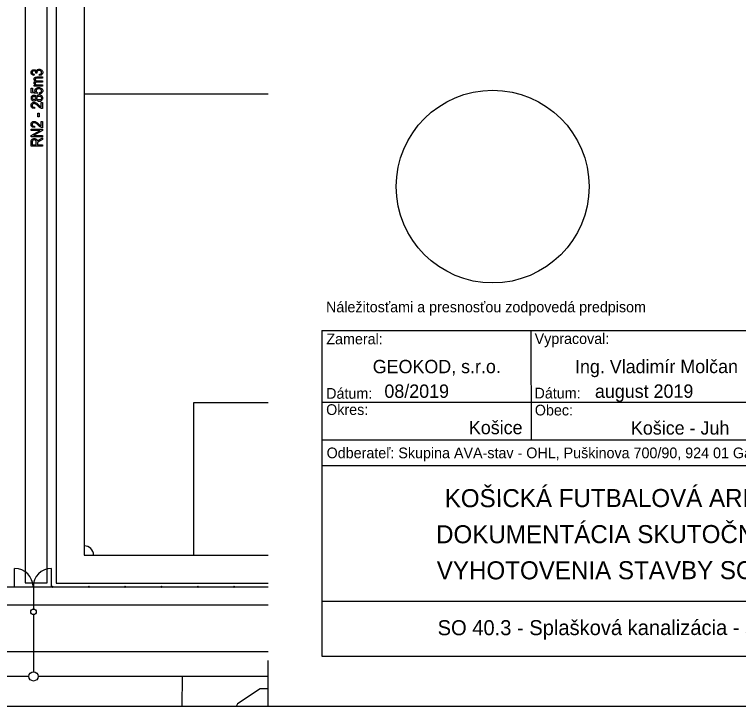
# Model space of a CAD drawing. Extents: x -264125 to -263915, y -1242307 to -1242159.
# Drawn here: x -264047.1 to -263968.6, y -1242307.4 to -1242232.4 of the extents above; entities that cross this region are included whole.
import ezdxf

# ---------------------------------------------------------------- set-up
doc = ezdxf.new("R2010")
doc.units = 0
for name, color, linetype in [('KFA_JESTV_IS_DSP', 7, 'Continuous'), ('KFA_SITUACIA_DSP', 7, 'Continuous'), ('RAM_NA_TLAC_A3_1-500', 7, 'Continuous'), ('ROZPISKA', 7, 'Continuous')]:
    doc.layers.add(name, color=color, linetype=linetype)

msp = doc.modelspace()

# ---------------------------------------------------------------- linework, layer by layer
at = {"layer": 'KFA_JESTV_IS_DSP'}
for p, q in [((-264020.458, -1242305.503), (-264022.907, -1242307.109)), ((-264019.579, -1242305.481), (-264020.458, -1242305.503)), ((-264022.907, -1242307.109), (-264023.062, -1242307.413))]:
    msp.add_line(p, q, dxfattribs=at)
at = {"layer": 'KFA_SITUACIA_DSP'}
for p, q in [((-264042.568, -1242187.932), (-264042.568, -1242294.032)), ((-264039.518, -1242190.982), (-264039.518, -1242290.982)), ((-264045.927, -1242194.982), (-264045.927, -1242293.982)), ((-264043.527, -1242293.982), (-264043.527, -1242194.982)), ((-264019.579, -1242240.982), (-264039.518, -1242240.982)), ((-264019.579, -1242274.482), (-264027.678, -1242274.482)), ((-264027.678, -1242274.482), (-264027.678, -1242290.982)), ((-264039.518, -1242290.982), (-264019.579, -1242290.982)), ((-264047.068, -1242294.432), (-264047.068, -1242292.432)), ((-264043.068, -1242294.432), (-264043.068, -1242292.432)), ((-264045.927, -1242293.982), (-264043.527, -1242293.982)), ((-264045.017, -1242293.982), (-264045.027, -1242296.847)), ((-264042.568, -1242294.032), (-264019.579, -1242294.032)), ((-264118.068, -1242294.432), (-264045.118, -1242294.432)), ((-264045.568, -1242294.432), (-264044.568, -1242294.432)), ((-264045.118, -1242294.432), (-264019.579, -1242294.432)), ((-264042.908, -1242294.432), (-264043.028, -1242294.432)), ((-264042.968, -1242294.492), (-264042.968, -1242294.372)), ((-264038.969, -1242294.432), (-264039.089, -1242294.432)), ((-264039.029, -1242294.492), (-264039.029, -1242294.372)), ((-264035.03, -1242294.432), (-264035.15, -1242294.432)), ((-264035.09, -1242294.492), (-264035.09, -1242294.372)), ((-264031.091, -1242294.432), (-264031.211, -1242294.432)), ((-264031.151, -1242294.492), (-264031.151, -1242294.372)), ((-264027.152, -1242294.432), (-264027.272, -1242294.432)), ((-264027.212, -1242294.492), (-264027.212, -1242294.372)), ((-264023.213, -1242294.432), (-264023.333, -1242294.432)), ((-264023.273, -1242294.492), (-264023.273, -1242294.372)), ((-264019.579, -1242296.432), (-264120.018, -1242296.432)), ((-264045.027, -1242297.447), (-264045.027, -1242303.647)), ((-264019.579, -1242301.482), (-264112.961, -1242301.482)), ((-264045.527, -1242304.147), (-264094.527, -1242304.147)), ((-264019.579, -1242304.147), (-264044.527, -1242304.147)), ((-264028.893, -1242307.413), (-264028.89, -1242304.147))]:
    msp.add_line(p, q, dxfattribs=at)
for points in [[(-264044.946, -1242238.832), (-264044.973, -1242238.957)], [(-264044.634, -1242238.721), (-264044.769, -1242238.707), (-264044.767, -1242238.687)], [(-264044.663, -1242239.118), (-264044.042, -1242239.118), (-264044.042, -1242239.244), (-264044.613, -1242239.244)], [(-264044.373, -1242238.97), (-264044.393, -1242238.844)], [(-264044.042, -1242240.126), (-264044.947, -1242240.126), (-264044.947, -1242240.013), (-264044.821, -1242240.013)], [(-264044.568, -1242239.559), (-264044.042, -1242239.559), (-264044.042, -1242239.685), (-264044.631, -1242239.685)], [(-264044.512, -1242240), (-264044.042, -1242240), (-264044.042, -1242240.126)], [(-264044.615, -1242240.818), (-264044.633, -1242240.937), (-264045.276, -1242240.837), (-264045.276, -1242240.328), (-264045.129, -1242240.328), (-264045.129, -1242240.738), (-264044.793, -1242240.792)], [(-264044.369, -1242240.959), (-264044.383, -1242240.827)], [(-264044.919, -1242242.413), (-264044.935, -1242242.542)], [(-264044.19, -1242241.888), (-264044.042, -1242241.888), (-264044.042, -1242242.566)], [(-264044.19, -1242242.391), (-264044.19, -1242241.888)], [(-264044.418, -1242243.439), (-264044.572, -1242243.439), (-264044.572, -1242243.053), (-264044.418, -1242243.053), (-264044.418, -1242243.439)], [(-264044.19, -1242243.959), (-264044.042, -1242243.959), (-264044.042, -1242244.637)], [(-264044.19, -1242244.462), (-264044.19, -1242243.959)], [(-264044.042, -1242245.607), (-264045.292, -1242245.607), (-264045.292, -1242245.468), (-264044.311, -1242244.929), (-264045.292, -1242244.929), (-264045.292, -1242244.8), (-264044.042, -1242244.8), (-264044.042, -1242244.938), (-264045.022, -1242245.476), (-264044.042, -1242245.476), (-264044.042, -1242245.607)], [(-264044.919, -1242244.483), (-264044.935, -1242244.612)], [(-264044.042, -1242246.637), (-264045.292, -1242246.637), (-264045.292, -1242246.182)], [(-264045.154, -1242246.177), (-264045.154, -1242246.501), (-264044.74, -1242246.501)], [(-264044.74, -1242246.501), (-264044.74, -1242246.209)], [(-264044.597, -1242246.345), (-264044.597, -1242246.501), (-264044.042, -1242246.501), (-264044.042, -1242246.637)], [(-264044.382, -1242245.912), (-264044.042, -1242245.733), (-264044.042, -1242245.904), (-264044.302, -1242246.04)]]:
    msp.add_lwpolyline(points, dxfattribs=at)
for centre, radius in [((-264042.968, -1242294.432), 0.06), ((-264039.029, -1242294.432), 0.06), ((-264035.09, -1242294.432), 0.06), ((-264031.151, -1242294.432), 0.06), ((-264027.212, -1242294.432), 0.06), ((-264023.273, -1242294.432), 0.06), ((-264045.027, -1242297.147), 0.3), ((-264045.027, -1242304.147), 0.5)]:
    msp.add_circle(centre, radius, dxfattribs=at)
for centre, radius, start, end in [((-264039.518, -1242290.982), 1, 0, 90), ((-264047.068, -1242294.432), 2, 0, 90), ((-264043.068, -1242294.432), 2, 90, 180)]:
    msp.add_arc(centre, radius, start, end, dxfattribs=at)
for points in [[(-264044.973, -1242238.957), (-264045.133, -1242238.933), (-264045.215, -1242238.85), (-264045.297, -1242238.766), (-264045.297, -1242238.647), (-264045.297, -1242238.523), (-264045.205, -1242238.436), (-264045.113, -1242238.349), (-264044.973, -1242238.349), (-264044.888, -1242238.349), (-264044.822, -1242238.386), (-264044.757, -1242238.423), (-264044.719, -1242238.489), (-264044.702, -1242238.428), (-264044.663, -1242238.388), (-264044.624, -1242238.348), (-264044.558, -1242238.323), (-264044.493, -1242238.299), (-264044.412, -1242238.299), (-264044.24, -1242238.299), (-264044.13, -1242238.4), (-264044.021, -1242238.502), (-264044.021, -1242238.643), (-264044.021, -1242238.774), (-264044.116, -1242238.866), (-264044.212, -1242238.957), (-264044.373, -1242238.97)], [(-264044.767, -1242238.687), (-264044.767, -1242238.594), (-264044.824, -1242238.536), (-264044.881, -1242238.478), (-264044.976, -1242238.478), (-264045.064, -1242238.478), (-264045.117, -1242238.527), (-264045.17, -1242238.576), (-264045.17, -1242238.645), (-264045.17, -1242238.718), (-264045.115, -1242238.768), (-264045.059, -1242238.818), (-264044.946, -1242238.832)], [(-264044.393, -1242238.844), (-264044.147, -1242238.805), (-264044.147, -1242238.645), (-264044.147, -1242238.559), (-264044.22, -1242238.496), (-264044.293, -1242238.433), (-264044.409, -1242238.433), (-264044.518, -1242238.433), (-264044.585, -1242238.491), (-264044.651, -1242238.549), (-264044.651, -1242238.633), (-264044.651, -1242238.669), (-264044.634, -1242238.721)], [(-264044.821, -1242240.013), (-264044.891, -1242239.976), (-264044.93, -1242239.917), (-264044.968, -1242239.858), (-264044.968, -1242239.788), (-264044.968, -1242239.71), (-264044.927, -1242239.656), (-264044.887, -1242239.602), (-264044.81, -1242239.579), (-264044.889, -1242239.534), (-264044.928, -1242239.476), (-264044.968, -1242239.419), (-264044.968, -1242239.348), (-264044.968, -1242239.241), (-264044.895, -1242239.18), (-264044.823, -1242239.118), (-264044.663, -1242239.118)], [(-264044.613, -1242239.244), (-264044.71, -1242239.244), (-264044.751, -1242239.258), (-264044.791, -1242239.272), (-264044.813, -1242239.304), (-264044.836, -1242239.335), (-264044.836, -1242239.375), (-264044.836, -1242239.456), (-264044.771, -1242239.508), (-264044.707, -1242239.559), (-264044.568, -1242239.559)], [(-264044.631, -1242239.685), (-264044.743, -1242239.685), (-264044.789, -1242239.719), (-264044.836, -1242239.754), (-264044.836, -1242239.814), (-264044.836, -1242239.901), (-264044.766, -1242239.951), (-264044.696, -1242240), (-264044.512, -1242240)], [(-264044.793, -1242240.792), (-264044.871, -1242240.701), (-264044.871, -1242240.598), (-264044.871, -1242240.47), (-264044.762, -1242240.374), (-264044.652, -1242240.279), (-264044.466, -1242240.279), (-264044.283, -1242240.279), (-264044.152, -1242240.374), (-264044.021, -1242240.47), (-264044.021, -1242240.63), (-264044.021, -1242240.763), (-264044.113, -1242240.854), (-264044.206, -1242240.946), (-264044.369, -1242240.959)], [(-264044.383, -1242240.827), (-264044.264, -1242240.811), (-264044.206, -1242240.757), (-264044.147, -1242240.703), (-264044.147, -1242240.632), (-264044.147, -1242240.542), (-264044.23, -1242240.477), (-264044.312, -1242240.413), (-264044.455, -1242240.413), (-264044.588, -1242240.413), (-264044.662, -1242240.475), (-264044.736, -1242240.538), (-264044.736, -1242240.632), (-264044.736, -1242240.689), (-264044.704, -1242240.739), (-264044.672, -1242240.789), (-264044.615, -1242240.818)], [(-264044.72, -1242241.561), (-264044.754, -1242241.636), (-264044.818, -1242241.675), (-264044.881, -1242241.714), (-264044.976, -1242241.714), (-264045.118, -1242241.714), (-264045.207, -1242241.63), (-264045.297, -1242241.546), (-264045.297, -1242241.419), (-264045.297, -1242241.291), (-264045.206, -1242241.207), (-264045.115, -1242241.122), (-264044.971, -1242241.122), (-264044.88, -1242241.122), (-264044.818, -1242241.16), (-264044.755, -1242241.197), (-264044.72, -1242241.273), (-264044.684, -1242241.18), (-264044.602, -1242241.13), (-264044.52, -1242241.081), (-264044.399, -1242241.081), (-264044.232, -1242241.081), (-264044.126, -1242241.177), (-264044.021, -1242241.274), (-264044.021, -1242241.417), (-264044.021, -1242241.562), (-264044.126, -1242241.659), (-264044.232, -1242241.755), (-264044.403, -1242241.755), (-264044.528, -1242241.755), (-264044.61, -1242241.704), (-264044.691, -1242241.652), (-264044.72, -1242241.561)], [(-264044.98, -1242241.584), (-264044.888, -1242241.584), (-264044.834, -1242241.536), (-264044.78, -1242241.488), (-264044.78, -1242241.417), (-264044.78, -1242241.348), (-264044.833, -1242241.3), (-264044.887, -1242241.251), (-264044.972, -1242241.251), (-264045.059, -1242241.251), (-264045.115, -1242241.301), (-264045.17, -1242241.351), (-264045.17, -1242241.419), (-264045.17, -1242241.487), (-264045.116, -1242241.536), (-264045.062, -1242241.584), (-264044.98, -1242241.584)], [(-264044.403, -1242241.626), (-264044.288, -1242241.626), (-264044.218, -1242241.564), (-264044.147, -1242241.503), (-264044.147, -1242241.417), (-264044.147, -1242241.33), (-264044.215, -1242241.27), (-264044.284, -1242241.21), (-264044.398, -1242241.21), (-264044.513, -1242241.21), (-264044.583, -1242241.272), (-264044.653, -1242241.334), (-264044.653, -1242241.42), (-264044.653, -1242241.506), (-264044.583, -1242241.566), (-264044.513, -1242241.626), (-264044.403, -1242241.626)], [(-264044.935, -1242242.542), (-264045.115, -1242242.528), (-264045.206, -1242242.44), (-264045.297, -1242242.352), (-264045.297, -1242242.208), (-264045.297, -1242242.051), (-264045.191, -1242241.971), (-264045.086, -1242241.89), (-264044.951, -1242241.89), (-264044.832, -1242241.89), (-264044.722, -1242241.953), (-264044.613, -1242242.016), (-264044.43, -1242242.193), (-264044.315, -1242242.305), (-264044.273, -1242242.338), (-264044.232, -1242242.371), (-264044.19, -1242242.391)], [(-264044.042, -1242242.566), (-264044.132, -1242242.569), (-264044.243, -1242242.512), (-264044.353, -1242242.455), (-264044.504, -1242242.305), (-264044.68, -1242242.129), (-264044.776, -1242242.074), (-264044.872, -1242242.02), (-264044.955, -1242242.02), (-264045.05, -1242242.02), (-264045.11, -1242242.075), (-264045.17, -1242242.131), (-264045.17, -1242242.213), (-264045.17, -1242242.3), (-264045.105, -1242242.356), (-264045.04, -1242242.413), (-264044.919, -1242242.413)], [(-264044.935, -1242244.612), (-264045.115, -1242244.599), (-264045.206, -1242244.511), (-264045.297, -1242244.422), (-264045.297, -1242244.279), (-264045.297, -1242244.122), (-264045.191, -1242244.041), (-264045.086, -1242243.961), (-264044.951, -1242243.961), (-264044.832, -1242243.961), (-264044.722, -1242244.024), (-264044.613, -1242244.087), (-264044.43, -1242244.263), (-264044.315, -1242244.376), (-264044.273, -1242244.409), (-264044.232, -1242244.441), (-264044.19, -1242244.462)], [(-264044.042, -1242244.637), (-264044.132, -1242244.639), (-264044.243, -1242244.583), (-264044.353, -1242244.526), (-264044.504, -1242244.375), (-264044.68, -1242244.199), (-264044.776, -1242244.145), (-264044.872, -1242244.09), (-264044.955, -1242244.09), (-264045.05, -1242244.09), (-264045.11, -1242244.146), (-264045.17, -1242244.202), (-264045.17, -1242244.283), (-264045.17, -1242244.371), (-264045.105, -1242244.427), (-264045.04, -1242244.483), (-264044.919, -1242244.483)], [(-264045.292, -1242246.182), (-264045.292, -1242246.04), (-264045.257, -1242245.972), (-264045.222, -1242245.904), (-264045.141, -1242245.861), (-264045.059, -1242245.817), (-264044.952, -1242245.817), (-264044.811, -1242245.817), (-264044.723, -1242245.891), (-264044.635, -1242245.964), (-264044.611, -1242246.105), (-264044.577, -1242246.048), (-264044.542, -1242246.018), (-264044.47, -1242245.958), (-264044.382, -1242245.912)], [(-264044.74, -1242246.209), (-264044.74, -1242246.113), (-264044.763, -1242246.064), (-264044.786, -1242246.014), (-264044.836, -1242245.985), (-264044.885, -1242245.956), (-264044.951, -1242245.956), (-264045.046, -1242245.956), (-264045.1, -1242246.012), (-264045.154, -1242246.067), (-264045.154, -1242246.177)], [(-264044.302, -1242246.04), (-264044.454, -1242246.12), (-264044.507, -1242246.16), (-264044.56, -1242246.201), (-264044.579, -1242246.239), (-264044.597, -1242246.277), (-264044.597, -1242246.345)]]:
    msp.add_open_spline(points, degree=3, dxfattribs=at)
at = {"layer": 'RAM_NA_TLAC_A3_1-500'}
msp.add_line((-264019.579, -1242307.413), (-264019.579, -1242302.413), dxfattribs=at)
msp.add_lwpolyline([(-264124.579, -1242158.913), (-263914.579, -1242158.913), (-263914.579, -1242307.413), (-264124.579, -1242307.413)], close=True, dxfattribs=at)
at = {"layer": 'ROZPISKA'}
for p, q in [((-264013.782, -1242266.64), (-264013.784, -1242301.933)), ((-264013.782, -1242266.64), (-263920.515, -1242266.639)), ((-263991.1, -1242266.638), (-263991.092, -1242278.493)), ((-264013.786, -1242274.385), (-263945.722, -1242274.386)), ((-264013.784, -1242278.488), (-263945.724, -1242278.487)), ((-264013.79, -1242281.267), (-263945.715, -1242281.259)), ((-264013.785, -1242295.983), (-263920.512, -1242295.979)), ((-264013.784, -1242301.933), (-263920.513, -1242301.933))]:
    msp.add_line(p, q, dxfattribs=at)
msp.add_circle((-263995.254, -1242251.022), 10.45, dxfattribs=at)

# ---------------------------------------------------------------- texts
for s, height, rotation, p in [('Náležitosťami a presnosťou zodpovedá predpisom', 1.15934, 0.00155, (-264013.317, -1242264.654)), ('Zameral:', 1.1593, 0.00155, (-264013.281, -1242268.126)), ('Vypracoval:', 1.15934, 0.00155, (-263990.701, -1242268.092)), ('GEOKOD, s.r.o.', 1.4488, 0.04559, (-264008.251, -1242271.266)), ('Ing. Vladimír Molčan', 1.44909, 0.04559, (-263986.32, -1242271.263)), ('Dátum:', 1.1593, 0.00155, (-264013.296, -1242274.029)), ('08/2019', 1.4488, 0.04559, (-264006.986, -1242273.938)), ('Dátum:', 1.1593, 0.00155, (-263990.712, -1242273.998)), ('august 2019', 1.4488, 0.04559, (-263984.162, -1242273.938)), ('Okres:', 1.1593, 0.00155, (-264013.303, -1242275.787)), ('Obec:', 1.1593, 0.00155, (-263990.68, -1242275.842)), ('Košice', 1.4494, 0.04559, (-263997.827, -1242277.879)), ('Košice - Juh', 1.4498, 0.04559, (-263980.259, -1242277.922)), ('Odberateľ: Skupina AVA-stav - OHL, Puškinova 700/90, 924 01 Galanta', 1.15904, 0.00155, (-264013.251, -1242280.484)), ('KOŠICKÁ FUTBALOVÁ ARÉNA', 1.95724, 0.04559, (-264000.449, -1242285.794)), ('DOKUMENTÁCIA SKUTOČNÉHO', 1.95724, 0.04559, (-264001.385, -1242289.709)), ('VYHOTOVENIA STAVBY SO 40.3', 1.95724, 0.04559, (-264001.306, -1242293.624)), ('SO 40.3 - Splašková kanalizácia - stavebné úpravy', 1.63063, 0.04559, (-264001.217, -1242299.68))]:
    msp.add_text(s, height=height, rotation=rotation, dxfattribs=at).set_placement(p)

doc.saveas('drawing.dxf')
